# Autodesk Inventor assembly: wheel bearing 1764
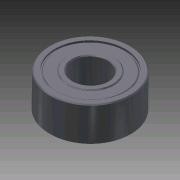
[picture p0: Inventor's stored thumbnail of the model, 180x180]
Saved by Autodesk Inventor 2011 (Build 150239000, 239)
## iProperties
Created: 2009-01
Part Number: wheel bearing 1764
Document SubType Name: Assembly
Designer: pmulligan
Author: pmulligan
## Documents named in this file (3)
- R:\CAD Archives\Wheels\Wheel bearing\wheel bearing 1764.iam
- R:\CAD Archives\Wheels\Wheel bearing\out casing 1764.ipt
- R:\CAD Archives\Wheels\Wheel bearing\inner ring 1764.ipt
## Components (2 placed, 2 different names)
1. out casing 1764:1 — Mate:1, Mate:2
2. inner ring 1764:1 — Mate:1, Mate:2, Angle:1, Mate:4
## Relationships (4: Mate 3, Angle 1)
- Mate:1: out casing 1764:1 ↔ inner ring 1764:1
- Mate:2: out casing 1764:1 ↔ inner ring 1764:1
- Angle:1: inner ring 1764:1
- Mate:4: inner ring 1764:1
